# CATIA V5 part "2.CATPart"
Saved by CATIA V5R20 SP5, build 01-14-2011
Part number: 2
Bounding box of the stored display mesh (mm): x -106.5 to -93.5, y -24 to 26, z 3.5 to 16.5
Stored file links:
  2.CATPart
  F:\CAD\很靠后、\1.CATPart
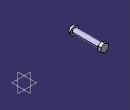
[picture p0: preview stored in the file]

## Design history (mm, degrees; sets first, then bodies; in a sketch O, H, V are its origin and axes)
Body1 (main body)
Body2
  Sketch1 on zx-plane, origin (0, 0, 0), H (-1, 0, 0), V (0, 0, 1)
    circle A1 centre (100, 10) radius 4
    radius A1 = 4
  Pad1: profile Sketch1, direction (0, 1, 0), length 21, mirrored extent
  Sketch2 on start face of Pad1, origin (0, -21, 0), H (1, 0, 0), V (0, 0, 1)
    circle A1 centre (-100, 10) radius 6.5
    radius A1 = 6.5
  Pad2: profile Sketch2, direction (0, -1, 0), length 3
  Sketch3 on end face of Pad1, origin (0, 21, 0), H (-1, 0, 0), V (0, 0, 1)
    point P1 (100, 10)
    point P2 (105.6292, 6.75)
    point P3 (105.6292, 13.25)
    point P4 (100, 16.5)
    point P5 (94.3708, 13.25)
    point P6 (94.3708, 6.75)
    point P7 (100, 3.5)
    point P8 (105.6292, 10)
    line L1 (105.6292, 6.75) -> (105.6292, 13.25)
    line L2 (105.6292, 13.25) -> (100, 16.5)
    line L3 (100, 16.5) -> (94.3708, 13.25)
    line L4 (94.3708, 13.25) -> (94.3708, 6.75)
    line L5 (94.3708, 6.75) -> (100, 3.5)
    line L6 (100, 3.5) -> (105.6292, 6.75)
    construction line L7 (100, 10) -> (105.6292, 10)
    construction circle A1 centre (100, 10) radius 6.5
    construction arc A2 centre (94.3708, 6.75) radius 6.5 from (94.3708, 13.25) to (100, 3.5) cw
    construction arc A3 centre (105.6292, 13.25) radius 6.5 from (100, 16.5) to (105.6292, 6.75) ccw
    radius A1 = 6.5
    coincidence: A1 P2, A1 P3, A1 P4, A1 P5, A1 P6, A1 P7, A2 P1, A3 P1
    midpoint: P8 L1
    parallelism: L1 L4
  Pad3: profile Sketch3, direction (0, 1, 0), length 5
